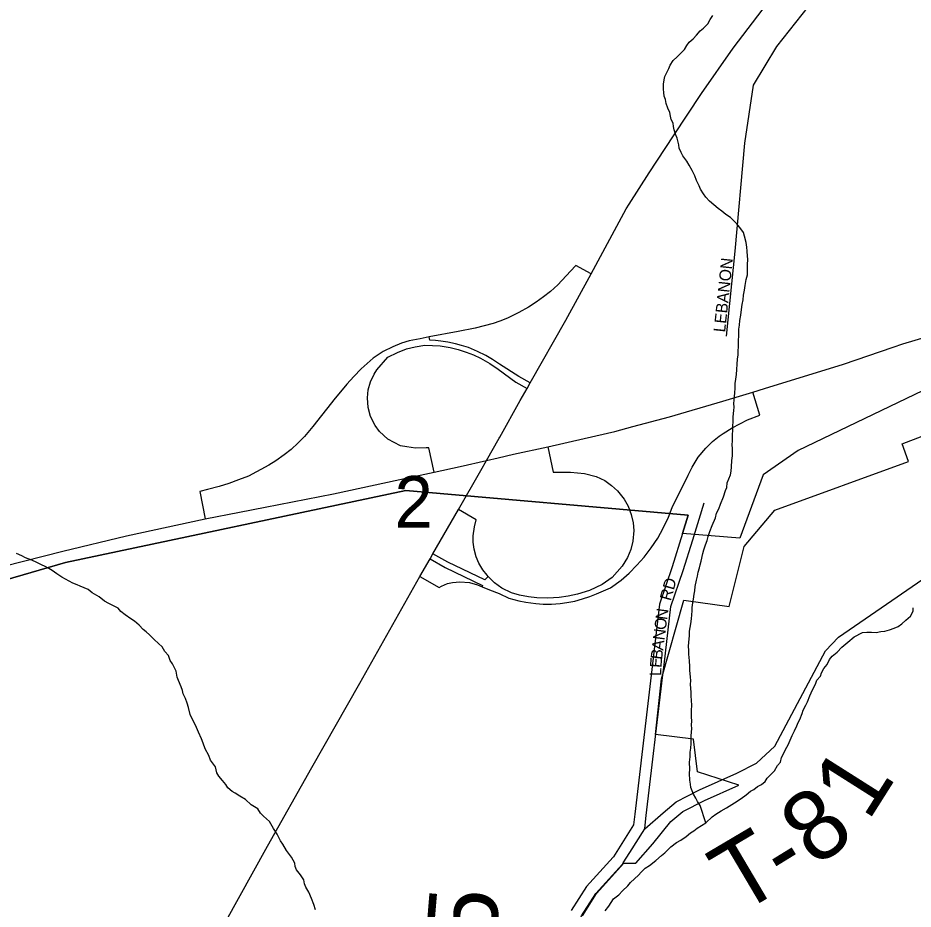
# Model space of a CAD drawing. Extents: x 1310247 to 1664935, y 284496 to 704931.
# Drawn here: x 1480374 to 1484208, y 506675 to 510491 of the extents above; entities that cross this region are included whole.
import ezdxf

# ---------------------------------------------------------------- set-up
doc = ezdxf.new("R2010")
doc.units = 0
for name, color, linetype in [('GM_X_Corporation_Text', 7, 'Continuous'), ('GM_X_County_Subdivision_Text', 7, 'Continuous'), ('GM_X_Interstate_Shield', 7, 'Continuous'), ('GM_X_Major_Lake_Text', 7, 'Continuous'), ('GM_X_Minor_River_Text', 7, 'Continuous'), ('GM_X_Rail_Line', 7, 'Continuous'), ('GM_X_State_Shield', 7, 'Continuous'), ('GM_X_Township_Subdivision', 7, 'Continuous'), ('GM_X_US_Location', 7, 'Continuous'), ('GM_X_US_Route', 7, 'Continuous')]:
    doc.layers.add(name, color=color, linetype=linetype)

msp = doc.modelspace()

# ---------------------------------------------------------------- linework, layer by layer
at = {"layer": 'GM_X_Corporation_Text'}
for points in [[(1483409.3, 509127.9), (1483445.8, 509492.6), (1483488, 509955.5), (1483524.6, 510203.8), (1483625.4, 510368.5), (1483923.7, 510746.8)], [(1483264.8, 508256.1), (1483313.9, 508414.2)], [(1483141.8, 507720.9), (1483171.1, 507969.8), (1483224.2, 508125.2), (1483264.8, 508256.1)], [(1483135.3, 507666), (1483141.8, 507720.9)]]:
    msp.add_lwpolyline(points, dxfattribs=at)
at = {"layer": 'GM_X_County_Subdivision_Text'}
for points in [[(1483058.9, 507018.2), (1483138.5, 507087.1), (1483193.6, 507134.4), (1483292.9, 507184.9), (1483452.9, 507256.5), (1483538.1, 507299.2), (1483615.7, 507372.2), (1483833.8, 507780), (1483889.2, 507839.2), (1484409.8, 508197.8)], [(1483064.2, 507063.1), (1483065.6, 507074.9), (1483135.3, 507666)], [(1482994.7, 506916.4), (1483058.9, 507018.2), (1483064.2, 507063.1)], [(1482672, 506288.5), (1482682.1, 506322.2), (1482745, 506531.8), (1482788.5, 506645.8), (1482849.1, 506741), (1482963.7, 506867.2), (1482966.8, 506872.1), (1482994.7, 506916.4)]]:
    msp.add_lwpolyline(points, dxfattribs=at)
at = {"layer": 'GM_X_Interstate_Shield'}
for points in [[(1482991.9, 509693.8), (1483077.4, 509828.3), (1483181.5, 509986.3), (1483302.3, 510168.1), (1483437.4, 510361.5), (1483584.5, 510554.7), (1483723.2, 510730), (1483813.6, 510834.1), (1483884.3, 510920.9)], [(1482526, 508852.1), (1482554.9, 508903.6), (1482568.6, 508928.3), (1482721.1, 509196.7), (1482829, 509395.8), (1482919, 509562.3), (1482979.4, 509674.1), (1482991.9, 509693.8)], [(1482356.6, 508553.5), (1482380.6, 508595.3), (1482435.5, 508691), (1482438.2, 508695.8), (1482526, 508852.1)], [(1480507.2, 505045.3), (1480521.5, 505099.1), (1480525.1, 505114.3), (1480578.6, 505299.1), (1480639.7, 505464.8), (1480706.6, 505604.9), (1480782.2, 505745.6), (1480906, 505973.4), (1481071.7, 506272.4), (1481260.6, 506615), (1481443, 506943.7), (1481633.7, 507280.3), (1481839, 507642.6), (1482096.1, 508098.5), (1482139.3, 508174.2), (1482151.7, 508195.9), (1482260.6, 508386.1), (1482356.6, 508553.5)]]:
    msp.add_lwpolyline(points, dxfattribs=at)
at = {"layer": 'GM_X_Major_Lake_Text'}
for points in [[(1486767.4, 510528.5), (1486537, 510381.4), (1486331.1, 510253.8), (1486113.1, 510124.4), (1485838.4, 509970.4), (1485630.6, 509848.8), (1485415.1, 509737.5), (1485224, 509639.6), (1485041.1, 509551.6), (1484878.8, 509481.1), (1484698.4, 509411.1), (1484481.6, 509333.9), (1484285.4, 509274.3), (1484249, 508894.7), (1483716.1, 508638.6), (1483565.7, 508534.4), (1483467, 508262.6), (1483221.1, 508283.6), (1483245.4, 508361.9), (1482035.8, 508467.7), (1480578.7, 508159.2), (1479277.2, 507780.4)], [(1482791.8, 506645.8), (1482852.3, 506741), (1482969.4, 506871), (1483020.6, 506871.2), (1483093.3, 506954), (1483171.1, 507049.3), (1483221.6, 507092.6), (1483314.5, 507139.8), (1483462.4, 507205.9), (1483285.2, 507262.8), (1483268.1, 507401.7), (1483105.1, 507421.8), (1483130.2, 507660.9), (1483226.7, 507997.3), (1483420.8, 507970.1), (1483484.9, 508227.2), (1483616, 508383.5), (1484188.3, 508591.8), (1484162.3, 508667.4), (1484516.1, 508803.2)], [(1479277.2, 507780.4), (1480578.7, 508159.2), (1482035.8, 508467.7), (1483245.4, 508361.9), (1483221.1, 508283.6), (1483176.7, 508140.7), (1483122.1, 507981), (1483016, 507080.7), (1483010.6, 507035.3), (1482924.5, 506898.7), (1482923.8, 506897.6), (1482809.2, 506771.5), (1482743.6, 506668.4)]]:
    msp.add_lwpolyline(points, dxfattribs=at)
at = {"layer": 'GM_X_Minor_River_Text'}
for points in [[(1483461.7, 509130), (1483462.6, 509158.1), (1483465.2, 509176), (1483465.9, 509196), (1483470.6, 509217.9), (1483473.4, 509241.9), (1483476.2, 509263.8), (1483480.8, 509283.7), (1483481.5, 509303.7), (1483486.2, 509325.6), (1483488.9, 509345.6), (1483493.8, 509371.5), (1483498.5, 509391.4), (1483499.3, 509415.4), (1483499.8, 509433.4), (1483500.6, 509457.4), (1483499.1, 509471.5), (1483497.7, 509491.6), (1483496.3, 509509.6), (1483493, 509529.8), (1483485.8, 509556.1), (1483482.3, 509572.2), (1483470.8, 509588.6), (1483453.4, 509609.1), (1483439.8, 509623.6), (1483426.2, 509636), (1483406.5, 509648.7), (1483388.9, 509663.2), (1483373.2, 509675.7), (1483355.6, 509690.3), (1483336.1, 509706.9), (1483320.6, 509723.4), (1483311, 509737.8), (1483297.6, 509758.2), (1483292, 509772.4), (1483280.7, 509794.8), (1483273.3, 509815), (1483262, 509837.4), (1483248.7, 509859.9), (1483239.3, 509878.2), (1483221.9, 509900.8), (1483214.4, 509915), (1483206.9, 509933.3), (1483205.4, 509947.4), (1483198.3, 509975.6), (1483190.8, 509993.9), (1483185.4, 510012.1), (1483181.9, 510026.2), (1483180.3, 510040.3), (1483172.8, 510056.6), (1483169.3, 510070.7), (1483165.8, 510086.8), (1483158.4, 510105.1), (1483151, 510125.4), (1483147.5, 510141.5), (1483141.9, 510155.7), (1483140.5, 510171.8), (1483138.9, 510185.8), (1483139.6, 510207.9), (1483142.3, 510225.8), (1483144.7, 510239.8), (1483153.3, 510257.5), (1483162, 510275.3), (1483168.5, 510289.1), (1483181.2, 510308.8), (1483197.8, 510324.3), (1483210.3, 510337.9), (1483228.9, 510355.4), (1483239.5, 510373.1), (1483250, 510386.8), (1483266.6, 510402.3), (1483281.2, 510417.9), (1483295.9, 510435.5), (1483310.3, 510447), (1483329, 510466.5), (1483339.7, 510484.2), (1483350.3, 510501.9)], [(1483320.4, 507044.7), (1483296.7, 507117.6), (1483285.3, 507136), (1483277.7, 507150.2), (1483268.2, 507166.5), (1483262.6, 507180.7), (1483257.1, 507194.9), (1483255.5, 507209), (1483252.1, 507227.1), (1483251, 507255.2), (1483251.6, 507273.2), (1483250.6, 507303.3), (1483253.4, 507327.3), (1483254.1, 507347.3), (1483256.6, 507363.2), (1483257.3, 507383.3), (1483257.7, 507397.3), (1483258.3, 507415.3), (1483258.9, 507433.3), (1483261.4, 507447.2), (1483259.9, 507463.3), (1483260.5, 507479.3), (1483259, 507497.4), (1483260, 507525.4), (1483260.7, 507547.4), (1483259.3, 507567.5), (1483258, 507587.6), (1483258.5, 507603.6), (1483255.6, 507635.8), (1483256.2, 507653.8), (1483254.6, 507667.8), (1483251.6, 507698), (1483252.1, 507714), (1483250.9, 507738.1), (1483249.4, 507752.2), (1483247.8, 507766.2), (1483248.4, 507782.2), (1483247, 507800.3), (1483247.5, 507816.3), (1483250.5, 507846.3), (1483251.1, 507864.3), (1483256.2, 507896.2), (1483258.9, 507918.2), (1483262, 507952.1), (1483262.5, 507966.1), (1483265.1, 507986.1), (1483267.7, 508002), (1483270.4, 508024), (1483272.9, 508037.9), (1483275.5, 508055.9), (1483280.4, 508083.8), (1483285, 508099.7), (1483287.6, 508117.6), (1483294.2, 508135.4), (1483296.7, 508149.4), (1483301.2, 508165.3), (1483308.3, 508197.1), (1483312.8, 508213), (1483319.6, 508234.8), (1483326.2, 508252.7), (1483330.8, 508270.6), (1483337.6, 508292.4), (1483348.5, 508318.1), (1483361.6, 508349.8), (1483366.2, 508369.6), (1483376.9, 508389.3), (1483383.6, 508409.2), (1483396.7, 508440.8), (1483405.6, 508466.6), (1483410.1, 508480.5), (1483412.7, 508500.4), (1483425.9, 508534.1), (1483428.5, 508550), (1483431.1, 508568), (1483432, 508596), (1483434.7, 508616), (1483435.6, 508646), (1483434.2, 508664.1), (1483434.7, 508678.1), (1483435.6, 508706.1), (1483436.3, 508726.1), (1483436.7, 508740.1), (1483437.6, 508766.1), (1483438.1, 508782.2), (1483441.1, 508810.1), (1483441.5, 508824.1), (1483440.1, 508840.2), (1483442.5, 508854.1), (1483445.6, 508886.1), (1483446.3, 508906.1), (1483446.9, 508926.1), (1483449.5, 508944.1), (1483452.2, 508964), (1483452.9, 508986.1), (1483455.6, 509008), (1483456.4, 509030), (1483459, 509048), (1483459.5, 509064), (1483460.2, 509084), (1483461, 509110), (1483461.7, 509130)], [(1481130.3, 507470.9), (1481120.9, 507489.3), (1481111.4, 507507.6), (1481104.4, 507537.9), (1481099, 507556.1), (1481091.6, 507576.3), (1481082.2, 507596.6), (1481078.7, 507610.8), (1481073.2, 507627), (1481062, 507653.4), (1481056.4, 507667.6), (1481051.3, 507693.8), (1481036.2, 507724.3), (1481026.6, 507738.6), (1481019.3, 507760.9), (1481003.8, 507777.4), (1480992.4, 507797.8), (1480976.8, 507812.3), (1480957.3, 507828.9), (1480937.9, 507849.5), (1480924.2, 507862), (1480910.5, 507872.4), (1480893, 507891), (1480873.5, 507907.6), (1480857.7, 507918.1), (1480834.2, 507934.9), (1480814.6, 507949.5), (1480803, 507963.9), (1480763.5, 507983.1), (1480745.7, 507993.7), (1480722.2, 508012.5), (1480692.6, 508029.4), (1480675, 508044), (1480641.3, 508057), (1480627.5, 508063.5), (1480609.6, 508070), (1480593.8, 508078.5), (1480578, 508087), (1480562.2, 508095.5), (1480540.6, 508110.2), (1480521, 508124.9), (1480507.2, 508133.3), (1480491.4, 508141.8), (1480475.5, 508148.3), (1480455.8, 508158.9), (1480434.1, 508169.6), (1480406.2, 508178.5), (1480390.4, 508187), (1480368.7, 508197.7)], [(1483653.7, 507339), (1483662.4, 507358.7), (1483673.1, 507378.4), (1483681.7, 507398.2), (1483690.4, 507418), (1483701.1, 507437.7), (1483709.9, 507459.5), (1483716.4, 507473.3), (1483722.9, 507487.1), (1483733.8, 507512.8), (1483738.2, 507526.7), (1483749, 507548.4), (1483755.5, 507562.2), (1483766.4, 507587.9), (1483777.3, 507613.6), (1483790.1, 507637.3), (1483796.7, 507655.1), (1483811.4, 507672.7), (1483815.9, 507686.6), (1483826.5, 507704.3), (1483841.1, 507721.9), (1483849.9, 507743.6), (1483862.4, 507757.3), (1483883.1, 507774.7), (1483903.9, 507796.1), (1483928.7, 507817.3), (1483955.6, 507840.6), (1483992.4, 507859.5), (1484010.5, 507860.9), (1484030.6, 507860.3), (1484050.6, 507859.7), (1484070.8, 507863), (1484087, 507864.5), (1484107.2, 507869.9), (1484127.6, 507877.3), (1484143.9, 507884.8), (1484160.3, 507896.3), (1484176.9, 507911.9), (1484197.6, 507929.3), (1484208.4, 507951), (1484208.8, 507965)], [(1481648.4, 506671.6), (1481641.1, 506693.8), (1481631.9, 506720.2), (1481620.7, 506746.6), (1481607.4, 506769), (1481601.9, 506783.2), (1481598.4, 506799.3), (1481585.1, 506821.8), (1481567.7, 506842.4), (1481562.1, 506856.6), (1481560.6, 506870.6), (1481545.4, 506897.1), (1481524.2, 506925.8), (1481509, 506952.4), (1481499.4, 506966.7), (1481491.9, 506980.9), (1481484.3, 506995.2), (1481469, 507019.7), (1481452, 507050.3), (1481426.6, 507073.1), (1481412.9, 507085.6), (1481401.5, 507103.9), (1481373.9, 507120.8), (1481348.5, 507143.6), (1481324.9, 507158.4), (1481305.3, 507171), (1481291.4, 507177.5), (1481273.9, 507194), (1481264.3, 507208.3), (1481250.8, 507224.8), (1481235.3, 507243.3), (1481225.7, 507257.6), (1481220.6, 507283.8), (1481199.4, 507312.5), (1481192, 507332.8), (1481176.9, 507361.3), (1481167.7, 507385.6), (1481160.2, 507403.9), (1481147.1, 507432.3), (1481139.7, 507452.6), (1481130.3, 507470.9)], [(1482890, 506667.3), (1482904.7, 506686.9), (1482925.9, 506718.3), (1482948.5, 506735.6), (1482963.2, 506753.2), (1482986, 506774.5), (1482998.5, 506788.2), (1483015.1, 506803.7), (1483031.7, 506819.2), (1483044.2, 506832.8), (1483060.8, 506850.4), (1483079.3, 506861.8), (1483106.1, 506883), (1483130.9, 506904.3), (1483145.4, 506915.9), (1483170.3, 506941.2), (1483195.1, 506960.4), (1483213.5, 506969.9), (1483236.1, 506985.2), (1483254.7, 507000.7), (1483269.1, 507010.2), (1483283.5, 507021.8), (1483302, 507033.3), (1483320.4, 507044.7), (1483347.4, 507069.9), (1483363.9, 507081.4), (1483386.4, 507094.8), (1483408.9, 507108.1), (1483443.8, 507129.1), (1483472.6, 507148.2), (1483493.2, 507163.6), (1483511.7, 507179), (1483526.1, 507186.6), (1483542.6, 507200.1), (1483558.9, 507207.6), (1483575.4, 507221.2), (1483583.9, 507234.9), (1483598.5, 507250.5), (1483615.1, 507266), (1483627.9, 507289.7), (1483640.4, 507303.3), (1483645.1, 507323.2), (1483653.7, 507339)]]:
    msp.add_lwpolyline(points, dxfattribs=at)
at = {"layer": 'GM_X_State_Shield'}
for points in [[(1484122.8, 509080.7), (1484165, 509094.9), (1484361.2, 509154.6), (1484578, 509231.8), (1484758.4, 509301.8), (1484920.7, 509372.3), (1485103.6, 509460.3), (1485294.7, 509558.2), (1485510.2, 509669.5), (1485718, 509791), (1485992.8, 509945.1), (1486210.7, 510074.5), (1486416.6, 510202.1), (1486647, 510349.2), (1486867.2, 510486.5), (1487132.3, 510658.9), (1487405.5, 510829.1), (1487624.5, 510969.9)], [(1483572.4, 508904.6), (1483909.9, 509008.6), (1484122.8, 509080.7)], [(1483007.9, 508741.1), (1483165.4, 508783.2), (1483393.9, 508850.1), (1483522.2, 508889.1), (1483572.4, 508904.6)], [(1482799.8, 508690.6), (1482930.9, 508720.5), (1483007.9, 508741.1)], [(1482380.6, 508595.3), (1482431.1, 508607), (1482496.7, 508622.2), (1482643.3, 508654.9), (1482799.8, 508690.6)], [(1482010.4, 508514.1), (1482157.3, 508545.2), (1482268.5, 508569.4), (1482380.6, 508595.3)], [(1481323.4, 508374.7), (1481432.9, 508396.2), (1481725.4, 508453.6), (1482010.4, 508514.1)], [(1478246.9, 507436.9), (1478451.7, 507526.8), (1478686.8, 507619.6), (1478903.7, 507702.8), (1479128.6, 507785.9), (1479316.9, 507847.7), (1479491.1, 507909.8), (1479691.4, 507971.4), (1479883.6, 508029.1), (1480108, 508090), (1480314.1, 508143.4), (1480566.7, 508207.7), (1480839.4, 508273.6), (1481176, 508345.6), (1481323.4, 508374.7)]]:
    msp.add_lwpolyline(points, dxfattribs=at)
at = {"layer": 'GM_X_US_Route'}
for points in [[(1482829, 509395.8), (1482764.1, 509430.9), (1482741.3, 509406.6), (1482686.4, 509348.7), (1482654.7, 509319.8), (1482625.7, 509296.2), (1482594.2, 509273.4), (1482561, 509252), (1482520.4, 509229.1), (1482471.3, 509206), (1482437.9, 509192.9), (1482409.7, 509183.2), (1482332.8, 509162.6), (1482259.3, 509148), (1482136.3, 509124.8), (1482097, 509117.3), (1482049.4, 509107.7), (1482016.7, 509097.8), (1481979.7, 509083.1), (1481939.3, 509062.1), (1481896.2, 509033.7), (1481844.2, 508988.5), (1481812.8, 508955.7), (1481782.5, 508922), (1481755.9, 508890.5), (1481733.7, 508862.7), (1481637, 508740.7), (1481601.8, 508699), (1481574.6, 508671), (1481544.3, 508643.4), (1481515.3, 508619.9), (1481479, 508594), (1481449.1, 508575.2), (1481361.3, 508528.8), (1481319.5, 508512.3), (1481277, 508497.2), (1481236.8, 508484.6), (1481186.8, 508471), (1481152.8, 508463.3), (1481176, 508345.6)], [(1482568.6, 508928.3), (1482520, 508955.6), (1482437.4, 509008.3), (1482407, 509028.8), (1482378.5, 509045.5), (1482342.7, 509063.3), (1482303.7, 509079.2), (1482274.2, 509088.9), (1482249.1, 509095.8), (1482215.8, 509102.9), (1482185.1, 509107.5), (1482163.3, 509109.8), (1482138.9, 509111.2), (1482136.3, 509124.8)], [(1482157.3, 508545.2), (1482134.6, 508649.9), (1482123.1, 508650.2), (1482077.4, 508648.7), (1482039.3, 508653.6), (1482013.3, 508658.7), (1481958.4, 508687.8), (1481923.4, 508719.9), (1481903.8, 508746.3), (1481885, 508784.2), (1481874.5, 508822.5), (1481871.4, 508864.7), (1481874.9, 508898.2), (1481884.7, 508933.2), (1481900.3, 508966), (1481912.1, 508984.2), (1481958.9, 509038.4), (1481999.9, 509058.9), (1482039.1, 509073.4), (1482076.3, 509083), (1482117.4, 509089.3), (1482183.3, 509086.5), (1482226.2, 509079.3), (1482259.3, 509071.2), (1482294.2, 509060.1), (1482325.3, 509047.9), (1482356.1, 509033.4), (1482395.4, 509011.1), (1482431.4, 508986.5), (1482506.6, 508930.6), (1482554.9, 508903.6)], [(1482096.1, 508098.5), (1482178.2, 508051.6), (1482188.5, 508057.9), (1482213.9, 508068.4), (1482235.4, 508073.8), (1482266.4, 508076.4), (1482308.5, 508073.7), (1482342, 508063.1), (1482362, 508054.9), (1482394.1, 508041.8), (1482435.9, 508026.4), (1482477.2, 508006.6), (1482519.9, 507994.3), (1482549, 507988.5), (1482592, 507982.8), (1482623.4, 507980.9), (1482659.2, 507981), (1482696.2, 507983.6), (1482724.9, 507987.4), (1482759, 507994), (1482792.3, 508002.8), (1482823.7, 508013.1), (1482852.2, 508024.4), (1482913, 508050.6), (1482958, 508082.7), (1482992.9, 508113.7), (1483025.7, 508146.9), (1483056, 508181.6), (1483086.7, 508221.9), (1483114.4, 508263.8), (1483138.2, 508305.9), (1483160.6, 508352.7), (1483177.1, 508393.9), (1483244.5, 508533), (1483261.7, 508567.8), (1483288.5, 508609.9), (1483320.4, 508648.9), (1483349.4, 508677.3), (1483377.9, 508700.5), (1483394.3, 508712), (1483432.8, 508735.7), (1483498.6, 508770.1), (1483552.2, 508790.4), (1483522.2, 508889.1)], [(1482643.3, 508654.9), (1482667.5, 508546.4), (1482701.4, 508546.5), (1482741.5, 508546.3), (1482801.5, 508540.6), (1482850.3, 508527.4), (1482887.5, 508509.6), (1482917.2, 508489.2), (1482942.8, 508465.8), (1482970.6, 508430.8), (1482987.8, 508399.9), (1483001.5, 508364.2), (1483009.1, 508329.3), (1483011.8, 508296), (1483008.2, 508250.9), (1482999.3, 508214.7), (1482984.8, 508179.9), (1482962.5, 508143.7), (1482919.7, 508095.1), (1482877.2, 508065.1), (1482822.5, 508039.7), (1482770.6, 508023), (1482730.9, 508014.1), (1482691.8, 508008.7), (1482644.1, 508006), (1482597.1, 508007.8), (1482561.4, 508012.1), (1482523.1, 508019.6), (1482488.3, 508029.1), (1482446.8, 508049), (1482415.8, 508071.7), (1482388.8, 508099), (1482383.9, 508104), (1482365.1, 508128.2), (1482348.8, 508156.4), (1482337.4, 508183.6), (1482328.7, 508215.9), (1482324.7, 508245.7), (1482324.4, 508273), (1482329.5, 508311.9), (1482337.3, 508342.1), (1482260.6, 508386.1)], [(1482139.3, 508174.2), (1482204.2, 508137.1), (1482364.3, 508060.6), (1482362, 508054.9)], [(1482388.8, 508099), (1482373.5, 508084), (1482215, 508159.7), (1482151.7, 508195.9)]]:
    msp.add_lwpolyline(points, dxfattribs=at)

# ---------------------------------------------------------------- texts
at = {"layer": 'GM_X_Rail_Line'}
for s, rotation, p in [('LEBANON', 83.946, (1483403.2, 509143.1)), ('RD', 74.4853, (1483170.4, 507991.9)), ('N', 82.7454, (1483154.6, 507911.4)), ('O', 82.7454, (1483149, 507867.8)), ('N', 82.7454, (1483143.5, 507824.1)), ('A', 82.7448, (1483137.9, 507780.5)), ('B', 82.9653, (1483133.1, 507741.2)), ('E', 86.0078, (1483130.7, 507706.8)), ('L', 89.5082, (1483130.4, 507672.4))]:
    msp.add_text(s, height=50, rotation=rotation, dxfattribs=at).set_placement(p)
at = {"layer": 'GM_X_Township_Subdivision'}
for s, rotation, p in [('1', 57.6595, (1484015.7, 507046.1)), ('8', 37.7243, (1483793.3, 506849.2)), ('T', 30.6124, (1483461.6, 506647.7)), ('-', 31.566, (1483659.4, 506764.8)), ('T-1085', 85.2924, (1482334.1, 505483.6))]:
    msp.add_text(s, height=300, rotation=rotation, dxfattribs=at).set_placement(p)
at = {"layer": 'GM_X_US_Location'}
msp.add_text('2', height=221, rotation=0, dxfattribs=at).set_placement((1481987, 508308.1))

doc.saveas('drawing.dxf')
